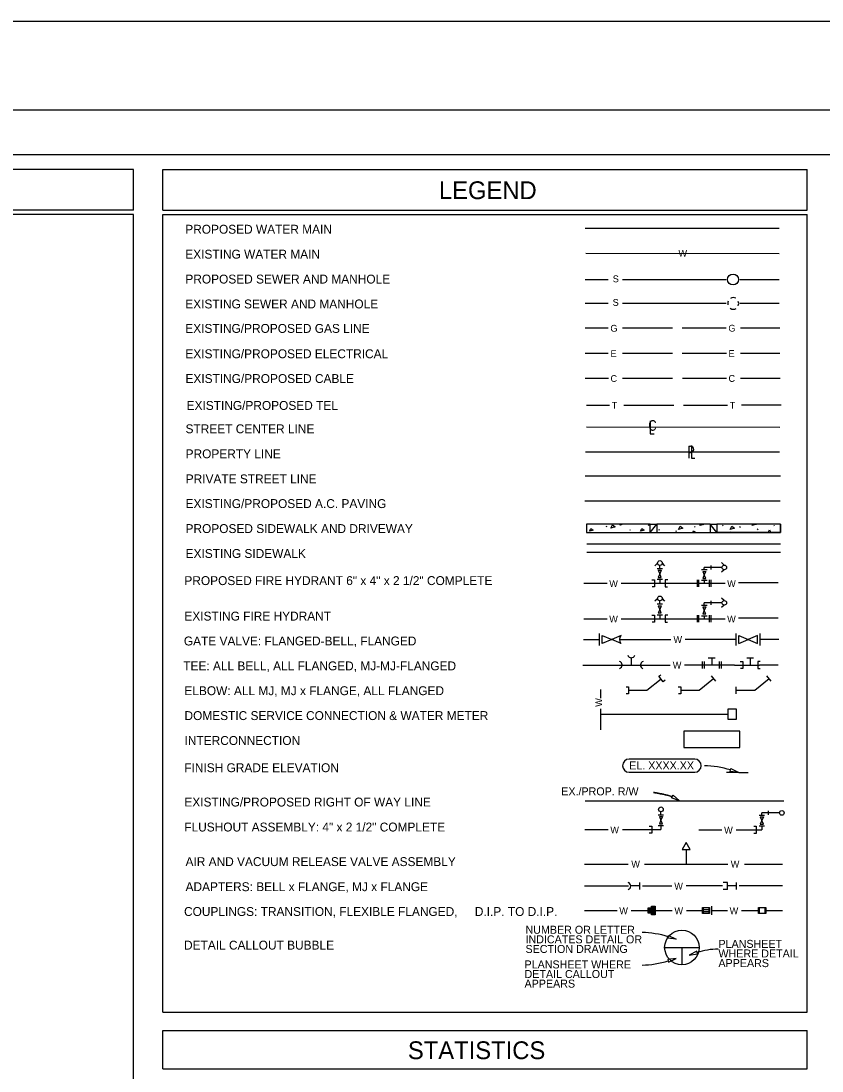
# Model space of a CAD drawing. Extents: x 837 to 1117, y 1316 to 1424.
# Drawn here: x 853.59 to 862.6, y 1410.43 to 1422.24 of the extents above; entities that cross this region are included whole.
import ezdxf

# ---------------------------------------------------------------- set-up
doc = ezdxf.new("R2010")
doc.units = 0
for name, color, linetype in [('0 (Construction)', 7, 'Continuous'), ('BASEMAP', 7, 'Continuous'), ('DIMS', 7, 'Continuous'), ('Existing AC Pavement', 7, 'Continuous'), ('Existing Sewer', 7, 'Continuous'), ('Existing Water', 7, 'Continuous'), ('LLINES', 7, 'Continuous'), ('lot lines', 7, 'Continuous'), ('Pvt and Future St', 7, 'Continuous'), ('Right-Of-Way', 7, 'Continuous'), ('Survey Control', 7, 'Continuous'), ('TEXT', 7, 'Continuous')]:
    doc.layers.add(name, color=color, linetype=linetype)

# ---------------------------------------------------------------- blocks, each defined once
blk = doc.blocks.new('ZPL_1')
at = {"layer": 'Existing Sewer'}
for p, q in [((0, 1213), (0, 0)), ((0, 0), (468, 0))]:
    blk.add_line(p, q, dxfattribs=at)
blk.add_text('C', height=1013, dxfattribs=at).set_placement((-208, 280))

msp = doc.modelspace()

# ---------------------------------------------------------------- linework, layer by layer
at = {"layer": '0 (Construction)'}
msp.add_lwpolyline([(841.77, 1422.24), (877.77, 1422.24), (877.77, 1398.24), (841.77, 1398.24)], close=True, dxfattribs=at)
at = {"layer": 'BASEMAP'}
for p, q in [((843.02, 1421.24), (877.02, 1421.24)), ((843.52, 1420.74), (876.52, 1420.74)), ((854.857, 1420.569), (843.678, 1420.569)), ((854.857, 1420.113), (854.857, 1420.569)), ((855.188, 1420.569), (862.436, 1420.569)), ((855.188, 1420.113), (855.188, 1420.569)), ((862.436, 1420.113), (862.436, 1420.569)), ((854.857, 1420.113), (843.678, 1420.113)), ((855.188, 1420.113), (862.436, 1420.113)), ((854.857, 1420.065), (843.678, 1420.065)), ((854.857, 1399.867), (854.857, 1420.065)), ((855.187, 1411.095), (855.188, 1420.065)), ((855.188, 1420.065), (862.436, 1420.065)), ((862.436, 1411.095), (862.436, 1420.065)), ((855.187, 1411.095), (862.436, 1411.095)), ((855.187, 1410.889), (862.435, 1410.889)), ((855.187, 1410.457), (855.187, 1410.889)), ((862.435, 1410.457), (862.435, 1410.889)), ((855.187, 1410.457), (862.435, 1410.457))]:
    msp.add_line(p, q, dxfattribs=at)
at = {"layer": 'DIMS'}
msp.add_line((860.13, 1415.241), (860.13, 1415.33), dxfattribs=at)
at = {"layer": 'Existing AC Pavement'}
msp.add_line((862.132, 1416.841), (859.935, 1416.841), dxfattribs=at)
at = {"layer": 'Existing Sewer'}
for p, q in [((861.104, 1417.459), (861.104, 1417.323)), ((861.104, 1417.459), (861.124, 1417.459)), ((861.104, 1417.387), (861.124, 1417.387)), ((861.134, 1417.467), (861.134, 1417.323)), ((861.134, 1417.323), (861.17, 1417.323))]:
    msp.add_line(p, q, dxfattribs=at)
msp.add_circle((861.601, 1419.333), 0.0617, dxfattribs=at)
msp.add_arc((861.124, 1417.423), 0.0358, 270, 90, dxfattribs=at)
at = {"layer": 'Existing Water'}
msp.add_line((859.944, 1419.628), (862.121, 1419.627), dxfattribs=at)
at = {"layer": 'LLINES'}
for p, q in [((859.936, 1419.91), (862.121, 1419.91)), ((859.937, 1419.333), (860.197, 1419.333)), ((860.357, 1419.333), (860.919, 1419.333)), ((860.919, 1419.333), (861.525, 1419.333)), ((861.676, 1419.333), (862.121, 1419.333)), ((859.936, 1419.068), (860.197, 1419.068)), ((860.356, 1419.068), (860.919, 1419.068)), ((860.919, 1419.068), (861.524, 1419.068)), ((861.676, 1419.068), (862.121, 1419.068)), ((859.936, 1418.788), (860.197, 1418.788)), ((860.357, 1418.788), (860.919, 1418.788)), ((861.029, 1418.788), (861.525, 1418.788)), ((861.684, 1418.788), (862.128, 1418.788)), ((859.937, 1418.503), (860.198, 1418.503)), ((860.358, 1418.503), (860.92, 1418.503)), ((861.03, 1418.503), (861.526, 1418.503)), ((861.685, 1418.503), (862.129, 1418.503)), ((859.938, 1418.223), (860.199, 1418.223)), ((860.358, 1418.223), (860.921, 1418.223)), ((861.031, 1418.223), (861.526, 1418.223)), ((861.685, 1418.223), (862.13, 1418.223)), ((859.951, 1417.921), (860.212, 1417.921)), ((860.371, 1417.921), (860.934, 1417.921)), ((861.044, 1417.921), (861.539, 1417.921)), ((861.698, 1417.922), (862.143, 1417.922)), ((860.177, 1416.553), (860.182, 1416.564)), ((860.333, 1416.571), (860.334, 1416.583)), ((860.669, 1416.489), (860.744, 1416.583)), ((860.669, 1416.583), (860.744, 1416.583)), ((860.744, 1416.583), (860.744, 1416.489)), ((861.344, 1416.583), (860.744, 1416.583)), ((861.169, 1416.556), (861.174, 1416.549)), ((861.344, 1416.583), (861.344, 1416.489)), ((861.419, 1416.489), (861.344, 1416.583)), ((861.344, 1416.583), (861.419, 1416.583)), ((862.135, 1416.583), (861.419, 1416.583)), ((861.484, 1416.57), (861.489, 1416.562)), ((861.679, 1416.545), (861.684, 1416.556)), ((862.06, 1416.57), (862.065, 1416.562)), ((862.135, 1416.583), (862.135, 1416.489)), ((860.439, 1416.522), (860.444, 1416.515)), ((860.669, 1416.489), (860.744, 1416.489)), ((860.744, 1416.489), (861.344, 1416.489)), ((860.765, 1416.524), (860.77, 1416.516)), ((860.96, 1416.499), (860.965, 1416.51)), ((861.341, 1416.524), (861.346, 1416.516)), ((861.344, 1416.489), (861.419, 1416.489)), ((862.135, 1416.489), (861.419, 1416.489)), ((861.575, 1416.489), (861.58, 1416.5)), ((861.878, 1416.518), (861.883, 1416.53)), ((859.955, 1416.359), (862.136, 1416.359)), ((859.955, 1416.266), (862.136, 1416.266)), ((860.751, 1416.142), (860.723, 1416.114)), ((860.746, 1416.083), (860.808, 1416.083)), ((860.76, 1416.063), (860.777, 1416.023)), ((860.76, 1416.063), (860.794, 1416.063)), ((860.777, 1416.083), (860.777, 1416.119)), ((860.794, 1416.063), (860.777, 1416.023)), ((860.804, 1416.144), (860.832, 1416.115)), ((861.246, 1416.071), (861.309, 1416.071)), ((861.278, 1416.071), (861.278, 1416.095)), ((861.351, 1416.118), (861.351, 1416.073)), ((861.501, 1416.122), (861.473, 1416.149)), ((861.501, 1416.069), (861.473, 1416.041)), ((860.746, 1415.963), (860.808, 1415.963)), ((860.777, 1416.023), (860.76, 1415.983)), ((860.76, 1415.983), (860.794, 1415.983)), ((860.794, 1415.983), (860.777, 1416.023)), ((860.777, 1415.963), (860.777, 1415.917)), ((861.202, 1415.878), (861.202, 1415.957)), ((861.218, 1415.878), (861.218, 1415.957)), ((861.246, 1415.951), (861.309, 1415.951)), ((861.261, 1416.051), (861.295, 1416.051)), ((861.261, 1416.051), (861.278, 1416.011)), ((861.278, 1416.011), (861.261, 1415.971)), ((861.261, 1415.971), (861.295, 1415.971)), ((861.295, 1416.051), (861.278, 1416.011)), ((861.295, 1415.971), (861.278, 1416.011)), ((861.278, 1415.951), (861.278, 1415.917)), ((861.338, 1415.878), (861.338, 1415.957)), ((861.354, 1415.878), (861.354, 1415.957)), ((859.923, 1415.917), (860.184, 1415.917)), ((860.344, 1415.917), (861.512, 1415.917)), ((861.663, 1415.927), (862.108, 1415.927)), ((860.751, 1415.744), (860.723, 1415.716)), ((860.777, 1415.685), (860.777, 1415.721)), ((860.804, 1415.745), (860.832, 1415.717)), ((861.351, 1415.72), (861.351, 1415.674)), ((861.501, 1415.723), (861.473, 1415.751)), ((860.746, 1415.685), (860.808, 1415.685)), ((860.76, 1415.665), (860.777, 1415.624)), ((860.76, 1415.665), (860.794, 1415.665)), ((860.777, 1415.624), (860.76, 1415.584)), ((860.794, 1415.665), (860.777, 1415.624)), ((860.794, 1415.584), (860.777, 1415.624)), ((861.246, 1415.672), (861.309, 1415.672)), ((861.261, 1415.652), (861.295, 1415.652)), ((861.261, 1415.652), (861.278, 1415.612)), ((861.278, 1415.612), (861.261, 1415.572)), ((861.278, 1415.672), (861.278, 1415.697)), ((861.295, 1415.652), (861.278, 1415.612)), ((861.295, 1415.572), (861.278, 1415.612)), ((861.501, 1415.671), (861.473, 1415.643)), ((859.923, 1415.519), (860.184, 1415.519)), ((860.344, 1415.519), (861.512, 1415.519)), ((860.746, 1415.564), (860.808, 1415.564)), ((860.76, 1415.584), (860.794, 1415.584)), ((860.777, 1415.564), (860.777, 1415.519)), ((861.202, 1415.479), (861.202, 1415.558)), ((861.218, 1415.479), (861.218, 1415.558)), ((861.246, 1415.552), (861.309, 1415.552)), ((861.261, 1415.572), (861.295, 1415.572)), ((861.278, 1415.552), (861.278, 1415.519)), ((861.338, 1415.479), (861.338, 1415.558)), ((861.354, 1415.479), (861.354, 1415.558)), ((861.663, 1415.529), (862.108, 1415.529)), ((860.1, 1415.219), (860.1, 1415.354)), ((861.637, 1415.218), (861.637, 1415.353)), ((861.907, 1415.218), (861.907, 1415.353)), ((859.92, 1415.286), (860.1, 1415.286)), ((860.13, 1415.33), (860.236, 1415.286)), ((860.236, 1415.286), (860.13, 1415.241)), ((860.341, 1415.33), (860.236, 1415.286)), ((860.341, 1415.241), (860.236, 1415.286)), ((860.325, 1415.286), (860.903, 1415.286)), ((861.637, 1415.286), (861.062, 1415.286)), ((861.667, 1415.241), (861.667, 1415.33)), ((861.667, 1415.33), (861.772, 1415.286)), ((861.667, 1415.241), (861.772, 1415.286)), ((861.878, 1415.33), (861.772, 1415.286)), ((861.772, 1415.286), (861.878, 1415.241)), ((861.878, 1415.241), (861.878, 1415.33)), ((862.118, 1415.286), (861.907, 1415.286)), ((859.913, 1414.998), (860.895, 1414.998)), ((860.456, 1415.08), (860.456, 1414.998)), ((861.617, 1414.998), (861.055, 1414.998)), ((861.256, 1414.959), (861.256, 1415.036)), ((861.28, 1414.959), (861.28, 1415.036)), ((861.323, 1415.08), (861.4, 1415.08)), ((861.362, 1415.08), (861.362, 1414.998)), ((861.444, 1415.036), (861.444, 1414.959)), ((861.467, 1415.036), (861.467, 1414.959)), ((861.617, 1414.998), (861.692, 1414.998)), ((861.69, 1414.998), (861.9, 1414.998)), ((861.757, 1415.08), (861.833, 1415.08)), ((861.795, 1415.08), (861.795, 1414.998)), ((862.11, 1414.998), (861.9, 1414.998)), ((860.633, 1414.714), (860.792, 1414.841)), ((861.219, 1414.714), (861.383, 1414.846)), ((861.407, 1414.816), (861.359, 1414.876)), ((861.847, 1414.714), (862.006, 1414.847)), ((862.031, 1414.817), (861.981, 1414.876)), ((860.11, 1414.721), (860.11, 1414.626)), ((860.426, 1414.714), (860.633, 1414.714)), ((861.013, 1414.714), (861.219, 1414.714)), ((861.637, 1414.675), (861.637, 1414.752)), ((861.637, 1414.714), (861.847, 1414.714)), ((860.11, 1414.507), (860.11, 1414.27)), ((860.11, 1414.446), (861.547, 1414.446)), ((861.547, 1414.507), (861.638, 1414.507)), ((861.547, 1414.384), (861.547, 1414.507)), ((861.638, 1414.507), (861.638, 1414.384)), ((861.638, 1414.384), (861.547, 1414.384)), ((861.665, 1413.789), (861.528, 1413.789)), ((861.665, 1413.789), (861.772, 1413.789)), ((860.79, 1413.313), (860.79, 1413.349)), ((861.998, 1413.358), (861.998, 1413.312)), ((860.758, 1413.313), (860.82, 1413.313)), ((860.773, 1413.293), (860.807, 1413.293)), ((860.773, 1413.293), (860.79, 1413.253)), ((860.79, 1413.253), (860.773, 1413.213)), ((860.807, 1413.293), (860.79, 1413.253)), ((860.807, 1413.213), (860.79, 1413.253)), ((861.894, 1413.31), (861.956, 1413.31)), ((861.908, 1413.29), (861.925, 1413.25)), ((861.908, 1413.29), (861.942, 1413.29)), ((861.925, 1413.25), (861.908, 1413.21)), ((861.925, 1413.31), (861.925, 1413.335)), ((861.942, 1413.29), (861.925, 1413.25)), ((861.942, 1413.21), (861.925, 1413.25)), ((859.935, 1413.147), (860.196, 1413.147)), ((860.356, 1413.147), (860.789, 1413.147)), ((860.758, 1413.193), (860.82, 1413.193)), ((860.773, 1413.213), (860.807, 1413.213)), ((860.789, 1413.193), (860.789, 1413.147)), ((861.216, 1413.144), (861.476, 1413.144)), ((861.636, 1413.144), (861.925, 1413.144)), ((861.894, 1413.19), (861.956, 1413.19)), ((861.908, 1413.21), (861.942, 1413.21)), ((861.925, 1413.19), (861.925, 1413.144)), ((859.932, 1412.759), (860.423, 1412.759)), ((860.604, 1412.759), (861.541, 1412.759)), ((861.73, 1412.759), (862.158, 1412.759)), ((860.553, 1412.475), (860.553, 1412.551)), ((861.537, 1412.475), (861.537, 1412.551)), ((861.64, 1412.475), (861.64, 1412.551)), ((859.93, 1412.513), (860.425, 1412.513)), ((860.583, 1412.513), (860.913, 1412.513)), ((861.482, 1412.513), (861.073, 1412.513)), ((862.157, 1412.513), (861.67, 1412.513)), ((861.364, 1412.19), (861.364, 1412.286)), ((859.929, 1412.238), (860.297, 1412.238)), ((860.457, 1412.238), (860.647, 1412.238)), ((860.724, 1412.238), (860.918, 1412.238)), ((861.077, 1412.238), (861.258, 1412.238)), ((861.258, 1412.203), (861.258, 1412.273)), ((861.258, 1412.273), (861.338, 1412.273)), ((861.338, 1412.203), (861.258, 1412.203)), ((861.267, 1412.203), (861.267, 1412.273)), ((861.267, 1412.25), (861.329, 1412.25)), ((861.267, 1412.227), (861.329, 1412.227)), ((861.329, 1412.273), (861.329, 1412.203)), ((861.338, 1412.273), (861.338, 1412.203)), ((861.364, 1412.238), (861.538, 1412.238)), ((861.698, 1412.238), (861.888, 1412.238)), ((861.888, 1412.273), (861.969, 1412.273)), ((861.888, 1412.203), (861.888, 1412.273)), ((861.969, 1412.203), (861.888, 1412.203)), ((861.898, 1412.203), (861.898, 1412.273)), ((861.959, 1412.273), (861.959, 1412.203)), ((861.969, 1412.273), (861.969, 1412.203)), ((861.969, 1412.238), (862.159, 1412.238)), ((860.832, 1411.822), (861.22, 1411.822)), ((861.026, 1411.822), (861.026, 1411.628))]:
    msp.add_line(p, q, dxfattribs=at)
for points in [[(860.669, 1416.583), (859.954, 1416.583), (859.954, 1416.489), (860.669, 1416.489), (860.669, 1416.583)], [(859.985, 1416.502), (860.001, 1416.534), (860.026, 1416.515), (859.985, 1416.502)], [(860.227, 1416.536), (860.246, 1416.574), (860.277, 1416.551), (860.227, 1416.536)], [(860.359, 1416.583), (860.334, 1416.571)], [(860.561, 1416.502), (860.577, 1416.534), (860.602, 1416.515), (860.561, 1416.502)], [(860.651, 1416.565), (860.66, 1416.583)], [(860.669, 1416.571), (860.651, 1416.565)], [(860.989, 1416.522), (861.007, 1416.56), (861.038, 1416.537), (860.989, 1416.522)], [(861.227, 1416.565), (861.236, 1416.583)], [(861.262, 1416.583), (861.268, 1416.578), (861.227, 1416.565)], [(862.135, 1416.583), (861.419, 1416.583), (861.419, 1416.489), (862.135, 1416.489), (862.135, 1416.583)], [(861.57, 1416.522), (861.588, 1416.56), (861.619, 1416.537), (861.57, 1416.522)], [(861.817, 1416.565), (861.825, 1416.583)], [(861.863, 1416.583), (861.866, 1416.581), (861.817, 1416.565)], [(861.15, 1416.489), (861.158, 1416.506), (861.181, 1416.489)], [(861.997, 1416.489), (862.013, 1416.519), (862.026, 1416.489)], [(860.689, 1415.957), (860.717, 1415.957), (860.717, 1415.878), (860.69, 1415.878)], [(860.866, 1415.957), (860.837, 1415.957), (860.837, 1415.878), (860.865, 1415.878)], [(860.689, 1415.558), (860.717, 1415.558), (860.717, 1415.479), (860.69, 1415.479)], [(860.866, 1415.558), (860.837, 1415.558), (860.837, 1415.479), (860.865, 1415.479)], [(861.683, 1415.037), (861.711, 1415.037), (861.711, 1414.958), (861.684, 1414.958)], [(861.907, 1415.037), (861.879, 1415.037), (861.879, 1414.958), (861.906, 1414.958)], [(860.839, 1414.827), (860.816, 1414.81), (860.767, 1414.871), (860.789, 1414.889)], [(860.398, 1414.753), (860.426, 1414.753), (860.426, 1414.674), (860.399, 1414.674)], [(860.985, 1414.753), (861.013, 1414.753), (861.013, 1414.674), (860.986, 1414.674)], [(861.17, 1413.94), (860.432, 1413.94)], [(860.432, 1413.793), (861.17, 1413.793)], [(860.658, 1413.187), (860.686, 1413.187), (860.686, 1413.108), (860.659, 1413.108)], [(861.835, 1413.184), (861.863, 1413.184), (861.863, 1413.105), (861.836, 1413.105)]]:
    msp.add_lwpolyline(points, dxfattribs=at)
msp.add_lwpolyline([(861.12, 1412.922), (861.074, 1413.001), (861.028, 1412.922)], close=True, dxfattribs=at)
for centre, radius in [((860.778, 1416.145), 0.0264), ((861.503, 1416.095), 0.0262), ((860.778, 1415.747), 0.0264), ((861.503, 1415.697), 0.0262), ((860.79, 1413.375), 0.0264), ((862.15, 1413.335), 0.0262), ((861.026, 1411.822), 0.194)]:
    msp.add_circle(centre, radius, dxfattribs=at)
for centre, radius, start, end in [((861.607, 1419.068), 0.0617, 66.0497, 122.8352), ((861.603, 1419.065), 0.0617, 157.9273, 196.2053), ((861.603, 1419.065), 0.0617, 334.8991, 21.4144), ((861.604, 1419.06), 0.0617, 235.65, 303.267), ((860.311, 1414.999), 0.0418, 289.7284, 71.9035), ((860.456, 1415.121), 0.0418, 198.0965, 340.2716), ((860.602, 1414.999), 0.0418, 108.0965, 250.2716), ((860.432, 1413.866), 0.0734, 90, 270), ((861.17, 1413.866), 0.0734, 270, 90), ((860.408, 1412.514), 0.0418, 289.7284, 71.9035)]:
    msp.add_arc(centre, radius, start, end, dxfattribs=at)
at = {"layer": 'lot lines'}
msp.add_line((859.94, 1417.396), (862.125, 1417.396), dxfattribs=at)
at = {"layer": 'Pvt and Future St'}
msp.add_line((862.134, 1417.12), (859.937, 1417.12), dxfattribs=at)
at = {"layer": 'Right-Of-Way'}
msp.add_line((859.938, 1413.469), (862.174, 1413.469), dxfattribs=at)
at = {"layer": 'Survey Control'}
msp.add_line((859.951, 1417.675), (862.128, 1417.673), dxfattribs=at)
at = {"layer": 'TEXT'}
for p, q in [((861.476, 1416.095), (861.278, 1416.095)), ((861.476, 1415.697), (861.278, 1415.697)), ((862.124, 1413.335), (861.925, 1413.335)), ((861.074, 1412.922), (861.074, 1412.759)), ((861.537, 1412.551), (861.49, 1412.551)), ((860.553, 1412.513), (860.45, 1412.513)), ((861.537, 1412.475), (861.49, 1412.475)), ((861.64, 1412.513), (861.537, 1412.513)), ((860.652, 1412.26), (860.68, 1412.26)), ((860.652, 1412.245), (860.68, 1412.245)), ((860.652, 1412.23), (860.68, 1412.23)), ((860.652, 1412.215), (860.68, 1412.215)), ((860.69, 1412.275), (860.718, 1412.275)), ((860.69, 1412.26), (860.718, 1412.26)), ((860.69, 1412.245), (860.718, 1412.245)), ((860.69, 1412.23), (860.718, 1412.23)), ((860.69, 1412.215), (860.718, 1412.215)), ((860.69, 1412.201), (860.719, 1412.201))]:
    msp.add_line(p, q, dxfattribs=at)
for points in [[(861.679, 1414.071), (861.679, 1414.254), (861.046, 1414.254), (861.046, 1414.071)], [(861.665, 1413.789), (861.568, 1413.802), (861.578, 1413.833)], [(860.999, 1413.469), (860.909, 1413.505), (860.926, 1413.533)], [(860.685, 1412.19), (860.685, 1412.286), (860.724, 1412.286), (860.724, 1412.19)], [(860.647, 1412.207), (860.647, 1412.269), (860.685, 1412.269), (860.685, 1412.207)], [(860.963, 1411.914), (860.867, 1411.927), (860.876, 1411.957)], [(860.963, 1411.699), (860.867, 1411.686), (860.876, 1411.656)], [(861.106, 1411.737), (861.202, 1411.75), (861.193, 1411.78)]]:
    msp.add_lwpolyline(points, close=True, dxfattribs=at)
for centre, radius, start, end in [((860.395, 1415.286), 0.0706, 140.7934, 219.2066), ((861.253, 1412.78), 1.086, 72.8735, 88.6667), ((861.253, 1412.78), 1.086, 72.8735, 88.6667), ((860.552, 1410.905), 1.086, 72.8735, 88.6667), ((860.552, 1410.905), 1.086, 72.8735, 88.6667), ((861.453, 1410.935), 0.869, 91.3333, 107.1265), ((861.453, 1410.935), 0.869, 91.3333, 107.1265), ((860.552, 1412.709), 1.086, 271.3333, 287.1265), ((860.552, 1412.709), 1.086, 271.3333, 287.1265)]:
    msp.add_arc(centre, radius, start, end, dxfattribs=at)
msp.add_open_spline([(860.917, 1413.518), (860.751, 1413.57), (860.577, 1413.574), (860.751, 1413.57), (860.917, 1413.518)], degree=4, dxfattribs=at)

# ---------------------------------------------------------------- block references
at = {"layer": 'Existing Sewer', "xscale": 9.437072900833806e-05, "yscale": 0.00011796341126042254, "rotation": 6.72683340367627e-10}
msp.add_blockref('ZPL_1', (860.668, 1417.599), dxfattribs=at)

# ---------------------------------------------------------------- texts
at = {"layer": 'Existing Sewer'}
msp.add_text('T', height=0.0768, dxfattribs=at).set_placement((860.236, 1417.879))
at = {"layer": 'LLINES'}
for s, height, p in [('LEGEND', 0.2, (858.293, 1420.237)), ('PROPOSED WATER MAIN', 0.1, (855.44, 1419.848)), ('EXISTING WATER MAIN ', 0.1, (855.44, 1419.568)), ('W ', 0.0768, (860.987, 1419.589)), ('PROPOSED SEWER AND MANHOLE', 0.1, (855.441, 1419.288)), ('S  ', 0.0768, (860.248, 1419.302)), ('EXISTING SEWER AND MANHOLE ', 0.1, (855.44, 1419.008)), ('S  ', 0.0768, (860.247, 1419.037)), ('EXISTING/PROPOSED GAS LINE', 0.1, (855.44, 1418.733)), ('G', 0.0768, (860.222, 1418.746)), ('G', 0.0768, (861.549, 1418.747)), ('EXISTING/PROPOSED ELECTRICAL', 0.1, (855.441, 1418.448)), ('E', 0.0768, (861.55, 1418.462)), ('E', 0.0768, (860.223, 1418.461)), ('EXISTING/PROPOSED CABLE', 0.1, (855.442, 1418.169)), ('C', 0.0768, (860.223, 1418.181)), ('C', 0.0768, (861.55, 1418.182)), ('EXISTING/PROPOSED TEL', 0.1, (855.455, 1417.867)), ('T', 0.0768, (861.563, 1417.88)), ('STREET CENTER LINE ', 0.1, (855.443, 1417.604)), ('PROPERTY LINE ', 0.1, (855.444, 1417.323)), ('PRIVATE STREET LINE', 0.1, (855.445, 1417.041)), ('EXISTING/PROPOSED A.C. PAVING ', 0.1, (855.443, 1416.763)), ('PROPOSED SIDEWALK AND DRIVEWAY', 0.1, (855.443, 1416.482)), ('EXISTING SIDEWALK', 0.1, (855.444, 1416.202)), ('PROPOSED FIRE HYDRANT 6" x 4" x 2 1/2" COMPLETE', 0.1, (855.43, 1415.897)), ('W ', 0.0768, (860.209, 1415.875)), ('W ', 0.0768, (861.535, 1415.875)), ('EXISTING FIRE HYDRANT ', 0.1, (855.43, 1415.498)), ('W ', 0.0768, (860.209, 1415.477)), ('W ', 0.0768, (861.535, 1415.477)), ('GATE VALVE: FLANGED-BELL, FLANGED', 0.1, (855.424, 1415.218)), ('W ', 0.0768, (860.931, 1415.246)), ('TEE: ALL BELL, ALL FLANGED, MJ-MJ-FLANGED', 0.1, (855.417, 1414.938)), ('W ', 0.0768, (860.923, 1414.958)), ('ELBOW: ALL MJ, MJ x FLANGE, ALL FLANGED', 0.1, (855.43, 1414.659)), ('DOMESTIC SERVICE CONNECTION & WATER METER', 0.1, (855.431, 1414.379)), ('INTERCONNECTION', 0.1, (855.432, 1414.099)), ('FINISH GRADE ELEVATION', 0.1, (855.429, 1413.793)), ('EL. XXXX.XX', 0.09, (860.433, 1413.824)), ('EX./PROP. R/W', 0.09, (859.669, 1413.532)), ('EXISTING/PROPOSED RIGHT OF WAY LINE ', 0.1, (855.43, 1413.407)), ('FLUSHOUT ASSEMBLY: 4" x 2 1/2" COMPLETE', 0.1, (855.429, 1413.126)), ('W ', 0.0768, (860.221, 1413.105)), ('W ', 0.0768, (861.501, 1413.102)), ('AIR AND VACUUM RELEASE VALVE ASSEMBLY', 0.1, (855.443, 1412.737)), ('W ', 0.0768, (860.457, 1412.721)), ('W ', 0.0768, (861.575, 1412.721)), ('ADAPTERS: BELL x FLANGE, MJ x FLANGE', 0.1, (855.443, 1412.455)), ('W ', 0.0768, (860.94, 1412.473)), ('COUPLINGS: TRANSITION, FLEXIBLE FLANGED,', 0.1, (855.426, 1412.176)), ('D.I.P. TO D.I.P.', 0.1, (858.697, 1412.176)), ('W ', 0.0768, (860.322, 1412.196)), ('W ', 0.0768, (860.942, 1412.196)), ('W ', 0.0768, (861.563, 1412.196)), ('NUMBER OR LETTER ', 0.09, (859.267, 1411.976)), ('INDICATES DETAIL OR ', 0.09, (859.267, 1411.868)), ('DETAIL CALLOUT BUBBLE', 0.1, (855.426, 1411.798)), ('SECTION DRAWING', 0.09, (859.267, 1411.76)), ('PLANSHEET ', 0.09, (861.437, 1411.817)), ('WHERE DETAIL ', 0.09, (861.437, 1411.709)), ('APPEARS', 0.09, (861.437, 1411.601)), ('PLANSHEET WHERE ', 0.09, (859.256, 1411.586)), ('APPEARS', 0.09, (859.256, 1411.37)), ('DETAIL CALLOUT ', 0.09, (859.256, 1411.478)), ('STATISTICS', 0.2, (857.944, 1410.566))]:
    msp.add_text(s, height=height, dxfattribs=at).set_placement(p)
msp.add_text('W ', height=0.0768, rotation=90, dxfattribs=at).set_placement((860.129, 1414.528))

doc.saveas('drawing.dxf')
